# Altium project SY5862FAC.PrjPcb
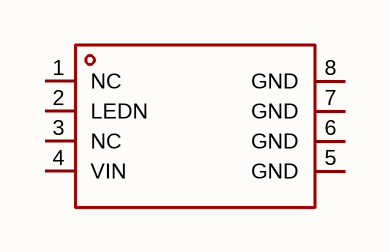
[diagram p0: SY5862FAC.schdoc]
1 sheet, 1 parts. Net scope: global (net labels, ports and power ports of the same name join across sheets).

## Sheet SY5862FAC.schdoc
size 127 x 101 mm

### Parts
U?  sy5862fac  [SO-8_L4.9-W3.9-P1.27-LS5.9-BL]  (value not drawn)

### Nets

Not connected (* = marked no-connect by the designer): U? 1(NC) 2(LEDN) 3(NC) 4(VIN) 5(GND) 6(GND) 7(GND) 8(GND)

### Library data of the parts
U? = sy5862fac: 类型:-;工作电压(DC):20V~60V;开关频率:-;通道数:1;输出电压:20V~60V;输出电流:1A;调光:-;拓扑结构:-;; Manufacturer: Silergy(矽力杰); AddInBom: yes; ModelId: 756fba4e187a48c69a2c935cd5c4465b; ModelName: SO-8_L4.9-W3.9-H1.5-LS5.9-P1.27; ModelTransform: 240.39054,192.913,0,270,0,0,0.0005,-0.0005,0; Number of Channels: 1; Output Current: 1A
